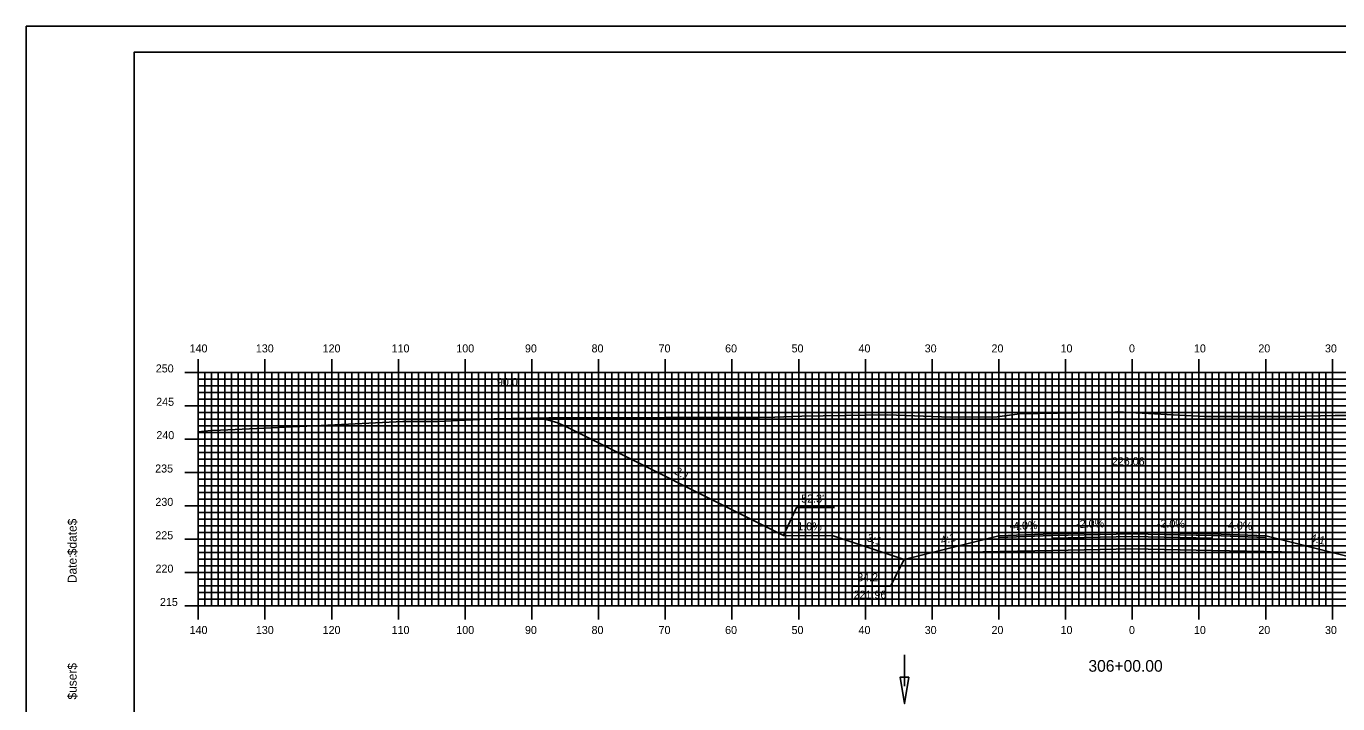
# Model space of a CAD drawing. Extents: x 1816883 to 1817226, y 442591 to 442811.
# Drawn here: x 1816882.8 to 1817079.4, y 442709 to 442810.5 of the extents above; entities that cross this region are included whole.
import ezdxf

# ---------------------------------------------------------------- set-up
doc = ezdxf.new("R2010")
doc.units = 0
for name, color, linetype in [('ANNOTATION', 7, 'Continuous'), ('BORDER', 7, 'Continuous'), ('D_Drainage_Ditch_Line', 7, 'Continuous'), ('D_Roadway_Centerline', 7, 'Continuous'), ('D_Roadway_Centerline_Text', 7, 'Continuous'), ('D_Roadway_Edge_Shoulder', 7, 'Continuous'), ('D_Roadway_Edge_TW', 7, 'Continuous'), ('D_Roadway_Pavement', 7, 'Continuous'), ('D_Roadway_SlopeLines', 7, 'Continuous'), ('D_Roadway_SubGrade', 7, 'Continuous'), ('D_Text_Standard', 7, 'Continuous'), ('H_V ANNOTATION', 7, 'Continuous'), ('MAJOR', 7, 'Continuous'), ('MINOR', 7, 'Continuous'), ('PLOT BOUNDARY', 7, 'Continuous'), ('S_Roadway_Centerline', 7, 'Continuous')]:
    doc.layers.add(name, color=color, linetype=linetype)

msp = doc.modelspace()

# ---------------------------------------------------------------- linework, layer by layer
at = {"layer": 'ANNOTATION'}
for points in [[(1817003.97, 442738.44), (1816998.28, 442738.44), (1816996.32, 442734.24)], [(1817006.64, 442726.64), (1817012.33, 442726.64), (1817014.41, 442730.62)]]:
    msp.add_lwpolyline(points, dxfattribs=at)
at = {"layer": 'BORDER'}
msp.add_lwpolyline([(1816898.99, 442596.67), (1817218.99, 442596.67), (1817218.99, 442806.67), (1816898.99, 442806.67)], close=True, dxfattribs=at)
at = {"layer": 'D_Drainage_Ditch_Line'}
msp.add_line((1817014.45, 442711.66), (1817014.45, 442716.36), dxfattribs=at)
msp.add_lwpolyline([(1817015.1, 442712.98), (1817013.79, 442712.98), (1817014.45, 442709.04)], close=True, dxfattribs=at)
at = {"layer": 'D_Roadway_Centerline'}
msp.add_lwpolyline([(1816958.59, 442751.81), (1816959.84, 442751.75), (1816961.09, 442751.53), (1816962.34, 442751.15), (1816963.59, 442750.61), (1816996.32, 442734.24), (1817003.78, 442734.16), (1817014.41, 442730.62), (1817018.41, 442731.62), (1817028.59, 442734.16), (1817036.59, 442734.48), (1817048.59, 442734.72), (1817060.59, 442734.48), (1817068.59, 442734.16), (1817078.76, 442731.62), (1817082.76, 442730.62), (1817093.39, 442734.16), (1817100.96, 442734.24), (1817133.59, 442750.55), (1817134.84, 442751.09), (1817136.09, 442751.46), (1817137.34, 442751.66), (1817138.59, 442751.68)], dxfattribs=at)
at = {"layer": 'D_Roadway_Edge_Shoulder'}
for points in [[(1817036.59, 442734.48), (1817028.59, 442734.16), (1817028.59, 442733.91), (1817036.59, 442734.23)], [(1817060.59, 442734.48), (1817068.59, 442734.16), (1817068.59, 442733.91), (1817060.59, 442734.23)]]:
    msp.add_lwpolyline(points, close=True, dxfattribs=at)
at = {"layer": 'D_Roadway_Edge_TW'}
msp.add_lwpolyline([(1817036.59, 442734.23), (1817036.59, 442734.48), (1817048.59, 442734.72), (1817060.59, 442734.48), (1817060.59, 442734.23), (1817048.59, 442734.47)], close=True, dxfattribs=at)
at = {"layer": 'D_Roadway_Pavement'}
msp.add_lwpolyline([(1817036.59, 442733.82), (1817036.59, 442734.23), (1817048.59, 442734.47), (1817060.59, 442734.23), (1817060.59, 442733.82), (1817048.59, 442734.06)], close=True, dxfattribs=at)
at = {"layer": 'D_Roadway_SlopeLines'}
for points in [[(1817003.78, 442734.16), (1816996.32, 442734.24), (1816963.59, 442750.61), (1816962.34, 442751.15), (1816961.09, 442751.53), (1816959.84, 442751.75), (1816958.59, 442751.81)], [(1817014.41, 442730.62), (1817003.78, 442734.16)], [(1817028.59, 442734.16), (1817014.41, 442730.62)], [(1817068.59, 442734.16), (1817082.76, 442730.62)]]:
    msp.add_lwpolyline(points, dxfattribs=at)
at = {"layer": 'D_Roadway_SubGrade'}
msp.add_lwpolyline([(1817036.59, 442731.98), (1817018.41, 442731.62), (1817028.59, 442734.16), (1817028.59, 442733.91), (1817036.59, 442734.23), (1817048.59, 442734.47), (1817060.59, 442734.23), (1817068.59, 442733.91), (1817068.59, 442734.16), (1817078.76, 442731.62), (1817060.59, 442731.98), (1817048.59, 442732.22)], close=True, dxfattribs=at)
at = {"layer": 'MAJOR'}
for p, q in [((1816908.59, 442760.67), (1816908.59, 442758.67)), ((1816918.59, 442760.67), (1816918.59, 442758.67)), ((1816928.59, 442760.67), (1816928.59, 442758.67)), ((1816938.59, 442760.67), (1816938.59, 442758.67)), ((1816948.59, 442760.67), (1816948.59, 442758.67)), ((1816958.59, 442760.67), (1816958.59, 442758.67)), ((1816968.59, 442760.67), (1816968.59, 442758.67)), ((1816978.59, 442760.67), (1816978.59, 442758.67)), ((1816988.59, 442760.67), (1816988.59, 442758.67)), ((1816998.59, 442760.67), (1816998.59, 442758.67)), ((1817008.59, 442760.67), (1817008.59, 442758.67)), ((1817018.59, 442760.67), (1817018.59, 442758.67)), ((1817028.59, 442760.67), (1817028.59, 442758.67)), ((1817038.59, 442760.67), (1817038.59, 442758.67)), ((1817048.59, 442760.67), (1817048.59, 442758.67)), ((1817058.59, 442760.67), (1817058.59, 442758.67)), ((1817068.59, 442760.67), (1817068.59, 442758.67)), ((1817078.59, 442760.67), (1817078.59, 442758.67)), ((1816906.58, 442758.67), (1816908.59, 442758.67)), ((1816908.59, 442758.67), (1817188.59, 442758.67)), ((1816908.59, 442723.67), (1816908.59, 442758.67)), ((1816908.59, 442723.67), (1816908.59, 442758.67)), ((1816908.59, 442758.67), (1817188.59, 442758.67)), ((1816918.59, 442723.67), (1816918.59, 442758.67)), ((1816928.59, 442723.67), (1816928.59, 442758.67)), ((1816938.59, 442723.67), (1816938.59, 442758.67)), ((1816948.59, 442723.67), (1816948.59, 442758.67)), ((1816958.59, 442723.67), (1816958.59, 442758.67)), ((1816968.59, 442723.67), (1816968.59, 442758.67)), ((1816978.59, 442723.67), (1816978.59, 442758.67)), ((1816988.59, 442723.67), (1816988.59, 442758.67)), ((1816998.59, 442723.67), (1816998.59, 442758.67)), ((1817008.59, 442723.67), (1817008.59, 442758.67)), ((1817018.59, 442723.67), (1817018.59, 442758.67)), ((1817028.59, 442723.67), (1817028.59, 442758.67)), ((1817038.59, 442723.67), (1817038.59, 442758.67)), ((1817048.59, 442723.67), (1817048.59, 442758.67)), ((1817058.59, 442723.67), (1817058.59, 442758.67)), ((1817068.59, 442723.67), (1817068.59, 442758.67)), ((1817078.59, 442723.67), (1817078.59, 442758.67)), ((1816906.58, 442753.67), (1816908.59, 442753.67)), ((1816908.59, 442753.67), (1817188.59, 442753.67)), ((1816906.58, 442748.67), (1816908.59, 442748.67)), ((1816908.59, 442748.67), (1817188.59, 442748.67)), ((1816906.58, 442743.67), (1816908.59, 442743.67)), ((1816908.59, 442743.67), (1817188.59, 442743.67)), ((1816906.58, 442738.67), (1816908.59, 442738.67)), ((1816908.59, 442738.67), (1817188.59, 442738.67)), ((1816906.58, 442733.67), (1816908.59, 442733.67)), ((1816908.59, 442733.67), (1817188.59, 442733.67)), ((1816906.58, 442728.67), (1816908.59, 442728.67)), ((1816908.59, 442728.67), (1817188.59, 442728.67)), ((1816906.58, 442723.67), (1816908.59, 442723.67)), ((1816908.59, 442723.67), (1817188.59, 442723.67)), ((1816908.59, 442723.67), (1817188.59, 442723.67)), ((1816908.59, 442721.66), (1816908.59, 442723.67)), ((1816918.59, 442721.66), (1816918.59, 442723.67)), ((1816928.59, 442721.66), (1816928.59, 442723.67)), ((1816938.59, 442721.66), (1816938.59, 442723.67)), ((1816948.59, 442721.66), (1816948.59, 442723.67)), ((1816958.59, 442721.66), (1816958.59, 442723.67)), ((1816968.59, 442721.66), (1816968.59, 442723.67)), ((1816978.59, 442721.66), (1816978.59, 442723.67)), ((1816988.59, 442721.66), (1816988.59, 442723.67)), ((1816998.59, 442721.66), (1816998.59, 442723.67)), ((1817008.59, 442721.66), (1817008.59, 442723.67)), ((1817018.59, 442721.66), (1817018.59, 442723.67)), ((1817028.59, 442721.66), (1817028.59, 442723.67)), ((1817038.59, 442721.66), (1817038.59, 442723.67)), ((1817048.59, 442721.66), (1817048.59, 442723.67)), ((1817058.59, 442721.66), (1817058.59, 442723.67)), ((1817068.59, 442721.66), (1817068.59, 442723.67)), ((1817078.59, 442721.66), (1817078.59, 442723.67))]:
    msp.add_line(p, q, dxfattribs=at)
at = {"layer": 'MINOR'}
for p, q in [((1816908.59, 442757.67), (1817188.59, 442757.67)), ((1816908.59, 442757.67), (1816910.59, 442757.67)), ((1816909.59, 442723.67), (1816909.59, 442758.67)), ((1816910.59, 442723.67), (1816910.59, 442758.67)), ((1816911.59, 442723.67), (1816911.59, 442758.67)), ((1816912.59, 442723.67), (1816912.59, 442758.67)), ((1816913.59, 442723.67), (1816913.59, 442758.67)), ((1816914.59, 442723.67), (1816914.59, 442758.67)), ((1816915.59, 442723.67), (1816915.59, 442758.67)), ((1816916.59, 442723.67), (1816916.59, 442758.67)), ((1816917.59, 442723.67), (1816917.59, 442758.67)), ((1816919.59, 442723.67), (1816919.59, 442758.67)), ((1816920.59, 442723.67), (1816920.59, 442758.67)), ((1816921.59, 442723.67), (1816921.59, 442758.67)), ((1816922.59, 442723.67), (1816922.59, 442758.67)), ((1816923.59, 442723.67), (1816923.59, 442758.67)), ((1816924.59, 442723.67), (1816924.59, 442758.67)), ((1816925.59, 442723.67), (1816925.59, 442758.67)), ((1816926.59, 442723.67), (1816926.59, 442758.67)), ((1816927.59, 442723.67), (1816927.59, 442758.67)), ((1816929.59, 442723.67), (1816929.59, 442758.67)), ((1816930.59, 442723.67), (1816930.59, 442758.67)), ((1816931.59, 442723.67), (1816931.59, 442758.67)), ((1816932.59, 442723.67), (1816932.59, 442758.67)), ((1816933.59, 442723.67), (1816933.59, 442758.67)), ((1816934.59, 442723.67), (1816934.59, 442758.67)), ((1816935.59, 442723.67), (1816935.59, 442758.67)), ((1816936.59, 442723.67), (1816936.59, 442758.67)), ((1816937.59, 442723.67), (1816937.59, 442758.67)), ((1816939.59, 442723.67), (1816939.59, 442758.67)), ((1816940.59, 442723.67), (1816940.59, 442758.67)), ((1816941.59, 442723.67), (1816941.59, 442758.67)), ((1816942.59, 442723.67), (1816942.59, 442758.67)), ((1816943.59, 442723.67), (1816943.59, 442758.67)), ((1816944.59, 442723.67), (1816944.59, 442758.67)), ((1816945.59, 442723.67), (1816945.59, 442758.67)), ((1816946.59, 442723.67), (1816946.59, 442758.67)), ((1816947.59, 442723.67), (1816947.59, 442758.67)), ((1816949.59, 442723.67), (1816949.59, 442758.67)), ((1816950.59, 442723.67), (1816950.59, 442758.67)), ((1816951.59, 442723.67), (1816951.59, 442758.67)), ((1816952.59, 442723.67), (1816952.59, 442758.67)), ((1816953.59, 442723.67), (1816953.59, 442758.67)), ((1816954.59, 442723.67), (1816954.59, 442758.67)), ((1816955.59, 442723.67), (1816955.59, 442758.67)), ((1816956.59, 442723.67), (1816956.59, 442758.67)), ((1816957.59, 442723.67), (1816957.59, 442758.67)), ((1816959.59, 442723.67), (1816959.59, 442758.67)), ((1816960.59, 442723.67), (1816960.59, 442758.67)), ((1816961.59, 442723.67), (1816961.59, 442758.67)), ((1816962.59, 442723.67), (1816962.59, 442758.67)), ((1816963.59, 442723.67), (1816963.59, 442758.67)), ((1816964.59, 442723.67), (1816964.59, 442758.67)), ((1816965.59, 442723.67), (1816965.59, 442758.67)), ((1816966.59, 442723.67), (1816966.59, 442758.67)), ((1816967.59, 442723.67), (1816967.59, 442758.67)), ((1816969.59, 442723.67), (1816969.59, 442758.67)), ((1816970.59, 442723.67), (1816970.59, 442758.67)), ((1816971.59, 442723.67), (1816971.59, 442758.67)), ((1816972.59, 442723.67), (1816972.59, 442758.67)), ((1816973.59, 442723.67), (1816973.59, 442758.67)), ((1816974.59, 442723.67), (1816974.59, 442758.67)), ((1816975.59, 442723.67), (1816975.59, 442758.67)), ((1816976.59, 442723.67), (1816976.59, 442758.67)), ((1816977.59, 442723.67), (1816977.59, 442758.67)), ((1816979.59, 442723.67), (1816979.59, 442758.67)), ((1816980.59, 442723.67), (1816980.59, 442758.67)), ((1816981.59, 442723.67), (1816981.59, 442758.67)), ((1816982.59, 442723.67), (1816982.59, 442758.67)), ((1816983.59, 442723.67), (1816983.59, 442758.67)), ((1816984.59, 442723.67), (1816984.59, 442758.67)), ((1816985.59, 442723.67), (1816985.59, 442758.67)), ((1816986.59, 442723.67), (1816986.59, 442758.67)), ((1816987.59, 442723.67), (1816987.59, 442758.67)), ((1816989.59, 442723.67), (1816989.59, 442758.67)), ((1816990.59, 442723.67), (1816990.59, 442758.67)), ((1816991.59, 442723.67), (1816991.59, 442758.67)), ((1816992.59, 442723.67), (1816992.59, 442758.67)), ((1816993.59, 442723.67), (1816993.59, 442758.67)), ((1816994.59, 442723.67), (1816994.59, 442758.67)), ((1816995.59, 442723.67), (1816995.59, 442758.67)), ((1816996.59, 442723.67), (1816996.59, 442758.67)), ((1816997.59, 442723.67), (1816997.59, 442758.67)), ((1816999.59, 442723.67), (1816999.59, 442758.67)), ((1817000.59, 442723.67), (1817000.59, 442758.67)), ((1817001.59, 442723.67), (1817001.59, 442758.67)), ((1817002.59, 442723.67), (1817002.59, 442758.67)), ((1817003.59, 442723.67), (1817003.59, 442758.67)), ((1817004.59, 442723.67), (1817004.59, 442758.67)), ((1817005.59, 442723.67), (1817005.59, 442758.67)), ((1817006.59, 442723.67), (1817006.59, 442758.67)), ((1817007.59, 442723.67), (1817007.59, 442758.67)), ((1817009.59, 442723.67), (1817009.59, 442758.67)), ((1817010.59, 442723.67), (1817010.59, 442758.67)), ((1817011.59, 442723.67), (1817011.59, 442758.67)), ((1817012.59, 442723.67), (1817012.59, 442758.67)), ((1817013.59, 442723.67), (1817013.59, 442758.67)), ((1817014.59, 442723.67), (1817014.59, 442758.67)), ((1817015.59, 442723.67), (1817015.59, 442758.67)), ((1817016.59, 442723.67), (1817016.59, 442758.67)), ((1817017.59, 442723.67), (1817017.59, 442758.67)), ((1817019.59, 442723.67), (1817019.59, 442758.67)), ((1817020.59, 442723.67), (1817020.59, 442758.67)), ((1817021.59, 442723.67), (1817021.59, 442758.67)), ((1817022.59, 442723.67), (1817022.59, 442758.67)), ((1817023.59, 442723.67), (1817023.59, 442758.67)), ((1817024.59, 442723.67), (1817024.59, 442758.67)), ((1817025.59, 442723.67), (1817025.59, 442758.67)), ((1817026.59, 442723.67), (1817026.59, 442758.67)), ((1817027.59, 442723.67), (1817027.59, 442758.67)), ((1817029.59, 442723.67), (1817029.59, 442758.67)), ((1817030.59, 442723.67), (1817030.59, 442758.67)), ((1817031.59, 442723.67), (1817031.59, 442758.67)), ((1817032.59, 442723.67), (1817032.59, 442758.67)), ((1817033.59, 442723.67), (1817033.59, 442758.67)), ((1817034.59, 442723.67), (1817034.59, 442758.67)), ((1817035.59, 442723.67), (1817035.59, 442758.67)), ((1817036.59, 442723.67), (1817036.59, 442758.67)), ((1817037.59, 442723.67), (1817037.59, 442758.67)), ((1817039.59, 442723.67), (1817039.59, 442758.67)), ((1817040.59, 442723.67), (1817040.59, 442758.67)), ((1817041.59, 442723.67), (1817041.59, 442758.67)), ((1817042.59, 442723.67), (1817042.59, 442758.67)), ((1817043.59, 442723.67), (1817043.59, 442758.67)), ((1817044.59, 442723.67), (1817044.59, 442758.67)), ((1817045.59, 442723.67), (1817045.59, 442758.67)), ((1817046.59, 442723.67), (1817046.59, 442758.67)), ((1817047.59, 442723.67), (1817047.59, 442758.67)), ((1817049.59, 442723.67), (1817049.59, 442758.67)), ((1817050.59, 442723.67), (1817050.59, 442758.67)), ((1817051.59, 442723.67), (1817051.59, 442758.67)), ((1817052.59, 442723.67), (1817052.59, 442758.67)), ((1817053.59, 442723.67), (1817053.59, 442758.67)), ((1817054.59, 442723.67), (1817054.59, 442758.67)), ((1817055.59, 442723.67), (1817055.59, 442758.67)), ((1817056.59, 442723.67), (1817056.59, 442758.67)), ((1817057.59, 442723.67), (1817057.59, 442758.67)), ((1817059.59, 442723.67), (1817059.59, 442758.67)), ((1817060.59, 442723.67), (1817060.59, 442758.67)), ((1817061.59, 442723.67), (1817061.59, 442758.67)), ((1817062.59, 442723.67), (1817062.59, 442758.67)), ((1817063.59, 442723.67), (1817063.59, 442758.67)), ((1817064.59, 442723.67), (1817064.59, 442758.67)), ((1817065.59, 442723.67), (1817065.59, 442758.67)), ((1817066.59, 442723.67), (1817066.59, 442758.67)), ((1817067.59, 442723.67), (1817067.59, 442758.67)), ((1817069.59, 442723.67), (1817069.59, 442758.67)), ((1817070.59, 442723.67), (1817070.59, 442758.67)), ((1817071.59, 442723.67), (1817071.59, 442758.67)), ((1817072.59, 442723.67), (1817072.59, 442758.67)), ((1817073.59, 442723.67), (1817073.59, 442758.67)), ((1817074.59, 442723.67), (1817074.59, 442758.67)), ((1817075.59, 442723.67), (1817075.59, 442758.67)), ((1817076.59, 442723.67), (1817076.59, 442758.67)), ((1817077.59, 442723.67), (1817077.59, 442758.67)), ((1816908.59, 442756.67), (1817188.59, 442756.67)), ((1816908.59, 442756.67), (1816910.59, 442756.67)), ((1816908.59, 442755.67), (1817188.59, 442755.67)), ((1816908.59, 442755.67), (1816910.59, 442755.67)), ((1816908.59, 442754.67), (1817188.59, 442754.67)), ((1816908.59, 442754.67), (1816910.59, 442754.67)), ((1816908.59, 442752.67), (1817188.59, 442752.67)), ((1816908.59, 442752.67), (1816910.59, 442752.67)), ((1816908.59, 442751.67), (1817188.59, 442751.67)), ((1816908.59, 442751.67), (1816910.59, 442751.67)), ((1816908.59, 442750.67), (1817188.59, 442750.67)), ((1816908.59, 442750.67), (1816910.59, 442750.67)), ((1816908.59, 442749.67), (1817188.59, 442749.67)), ((1816908.59, 442749.67), (1816910.59, 442749.67)), ((1816908.59, 442747.67), (1817188.59, 442747.67)), ((1816908.59, 442747.67), (1816910.59, 442747.67)), ((1816908.59, 442746.67), (1817188.59, 442746.67)), ((1816908.59, 442746.67), (1816910.59, 442746.67)), ((1816908.59, 442745.67), (1817188.59, 442745.67)), ((1816908.59, 442745.67), (1816910.59, 442745.67)), ((1816908.59, 442744.67), (1817188.59, 442744.67)), ((1816908.59, 442744.67), (1816910.59, 442744.67)), ((1816908.59, 442742.67), (1817188.59, 442742.67)), ((1816908.59, 442742.67), (1816910.59, 442742.67)), ((1816908.59, 442741.67), (1817188.59, 442741.67)), ((1816908.59, 442741.67), (1816910.59, 442741.67)), ((1816908.59, 442740.67), (1817188.59, 442740.67)), ((1816908.59, 442740.67), (1816910.59, 442740.67)), ((1816908.59, 442739.67), (1817188.59, 442739.67)), ((1816908.59, 442739.67), (1816910.59, 442739.67)), ((1816908.59, 442737.67), (1817188.59, 442737.67)), ((1816908.59, 442737.67), (1816910.59, 442737.67)), ((1816908.59, 442736.67), (1817188.59, 442736.67)), ((1816908.59, 442736.67), (1816910.59, 442736.67)), ((1816908.59, 442735.67), (1817188.59, 442735.67)), ((1816908.59, 442735.67), (1816910.59, 442735.67)), ((1816908.59, 442734.67), (1817188.59, 442734.67)), ((1816908.59, 442734.67), (1816910.59, 442734.67)), ((1816908.59, 442732.67), (1817188.59, 442732.67)), ((1816908.59, 442732.67), (1816910.59, 442732.67)), ((1816908.59, 442731.67), (1817188.59, 442731.67)), ((1816908.59, 442731.67), (1816910.59, 442731.67)), ((1816908.59, 442730.67), (1817188.59, 442730.67)), ((1816908.59, 442730.67), (1816910.59, 442730.67)), ((1816908.59, 442729.67), (1817188.59, 442729.67)), ((1816908.59, 442729.67), (1816910.59, 442729.67)), ((1816908.59, 442727.67), (1817188.59, 442727.67)), ((1816908.59, 442727.67), (1816910.59, 442727.67)), ((1816908.59, 442726.67), (1817188.59, 442726.67)), ((1816908.59, 442726.67), (1816910.59, 442726.67)), ((1816908.59, 442725.67), (1817188.59, 442725.67)), ((1816908.59, 442725.67), (1816910.59, 442725.67)), ((1816908.59, 442724.67), (1817188.59, 442724.67)), ((1816908.59, 442724.67), (1816910.59, 442724.67))]:
    msp.add_line(p, q, dxfattribs=at)
at = {"layer": 'PLOT BOUNDARY'}
msp.add_lwpolyline([(1816882.8, 442590.55), (1817222.8, 442590.55), (1817222.8, 442810.55), (1816882.8, 442810.55)], close=True, dxfattribs=at)
at = {"layer": 'S_Roadway_Centerline'}
msp.add_lwpolyline([(1816908.59, 442749.79), (1816910.49, 442749.95), (1816911.91, 442750.03), (1816917.39, 442750.25), (1816927, 442750.7), (1816939.25, 442751.31), (1816944.56, 442751.33), (1816952.9, 442751.7), (1816961.16, 442751.86), (1816978.73, 442751.91), (1816979.25, 442751.92), (1816979.56, 442751.93), (1816980.89, 442751.93), (1816992.65, 442751.92), (1816995, 442751.98), (1816999.04, 442752.12), (1817011.91, 442752.33), (1817021.37, 442751.95), (1817028.32, 442751.99), (1817031.69, 442752.48), (1817046, 442752.73), (1817046.31, 442752.74), (1817059.41, 442752.04), (1817062.7, 442752.04), (1817072.35, 442752.04), (1817079.03, 442752.2), (1817086.7, 442752.23)], dxfattribs=at)

# ---------------------------------------------------------------- texts
at = {"layer": 'ANNOTATION'}
for s, rotation, p in [('2:1', 333.4349, (1816979.89, 442743.49)), ('1.0%', 359.4271, (1816998.38, 442735.02)), ('-4.0%', 2.2906, (1817030.22, 442735.03)), ('-2.0%', 1.1458, (1817040.19, 442735.36)), ('-2.0%', 358.8542, (1817052.27, 442735.45)), ('-4.0%', 357.7094, (1817062.38, 442735.21)), ('3:1', 341.5651, (1817008.7, 442733.43)), ('4:1', 14.0362, (1817020.03, 442732.89)), ('4:1', 345.9638, (1817075.18, 442733.38))]:
    msp.add_text(s, height=1.2, rotation=rotation, dxfattribs=at).set_placement(p)
for s, p in [("52.3'", (1816998.97, 442739.17)), ("34.2'", (1817007.37, 442727.37)), ('221.96', (1817006.82, 442724.77))]:
    msp.add_text(s, height=1.2, dxfattribs=at).set_placement(p)
at = {"layer": 'BORDER'}
for s, p in [('$date$', (1816890.36, 442731.28)), ('Date:', (1816890.36, 442727.1)), ('$user$', (1816890.36, 442709.65))]:
    msp.add_text(s, height=1.339, rotation=90, dxfattribs=at).set_placement(p)
at = {"layer": 'D_Roadway_Centerline'}
for s, p in [('C', (1817048.58, 442734.72)), ('L', (1817048.59, 442734.72))]:
    msp.add_text(s, height=0.0146, dxfattribs=at).set_placement(p)
at = {"layer": 'D_Roadway_Centerline_Text'}
msp.add_text('226.06', height=1.2, dxfattribs=at).set_placement((1817045.53, 442744.75))
at = {"layer": 'D_Text_Standard'}
msp.add_text("90.0'", height=1.2, dxfattribs=at).set_placement((1816953.35, 442756.64))
at = {"layer": 'H_V ANNOTATION'}
for s, height, p in [('140', 1.2, (1816907.29, 442761.67)), ('130', 1.2, (1816917.22, 442761.67)), ('120', 1.2, (1816927.23, 442761.67)), ('110', 1.2, (1816937.57, 442761.67)), ('100', 1.2, (1816947.27, 442761.67)), ('90', 1.2, (1816957.56, 442761.67)), ('80', 1.2, (1816967.54, 442761.67)), ('70', 1.2, (1816977.59, 442761.67)), ('60', 1.2, (1816987.56, 442761.67)), ('50', 1.2, (1816997.52, 442761.67)), ('40', 1.2, (1817007.56, 442761.67)), ('30', 1.2, (1817017.48, 442761.67)), ('20', 1.2, (1817027.49, 442761.67)), ('10', 1.2, (1817037.84, 442761.67)), ('0', 1.2, (1817048.1, 442761.67)), ('10', 1.2, (1817057.84, 442761.67)), ('20', 1.2, (1817067.49, 442761.67)), ('30', 1.2, (1817077.48, 442761.67)), ('250', 1.2, (1816902.22, 442758.67)), ('245', 1.2, (1816902.28, 442753.67)), ('240', 1.2, (1816902.31, 442748.67)), ('235', 1.2, (1816902.13, 442743.67)), ('230', 1.2, (1816902.16, 442738.67)), ('225', 1.2, (1816902.15, 442733.67)), ('220', 1.2, (1816902.18, 442728.67)), ('215', 1.2, (1816902.84, 442723.67)), ('140', 1.2, (1816907.29, 442719.47)), ('130', 1.2, (1816917.22, 442719.47)), ('120', 1.2, (1816927.23, 442719.47)), ('110', 1.2, (1816937.57, 442719.47)), ('100', 1.2, (1816947.27, 442719.47)), ('90', 1.2, (1816957.56, 442719.47)), ('80', 1.2, (1816967.54, 442719.47)), ('70', 1.2, (1816977.59, 442719.47)), ('60', 1.2, (1816987.56, 442719.47)), ('50', 1.2, (1816997.52, 442719.47)), ('40', 1.2, (1817007.56, 442719.47)), ('30', 1.2, (1817017.48, 442719.47)), ('20', 1.2, (1817027.49, 442719.47)), ('10', 1.2, (1817037.84, 442719.47)), ('0', 1.2, (1817048.1, 442719.47)), ('10', 1.2, (1817057.84, 442719.47)), ('20', 1.2, (1817067.49, 442719.47)), ('30', 1.2, (1817077.48, 442719.47)), ('306+00.00', 1.75, (1817042.02, 442713.82))]:
    msp.add_text(s, height=height, dxfattribs=at).set_placement(p)
at = {"layer": 'MAJOR'}
msp.add_text('-', height=0.012, dxfattribs=at).set_placement((1816908.58, 442723.67))

doc.saveas('drawing.dxf')
